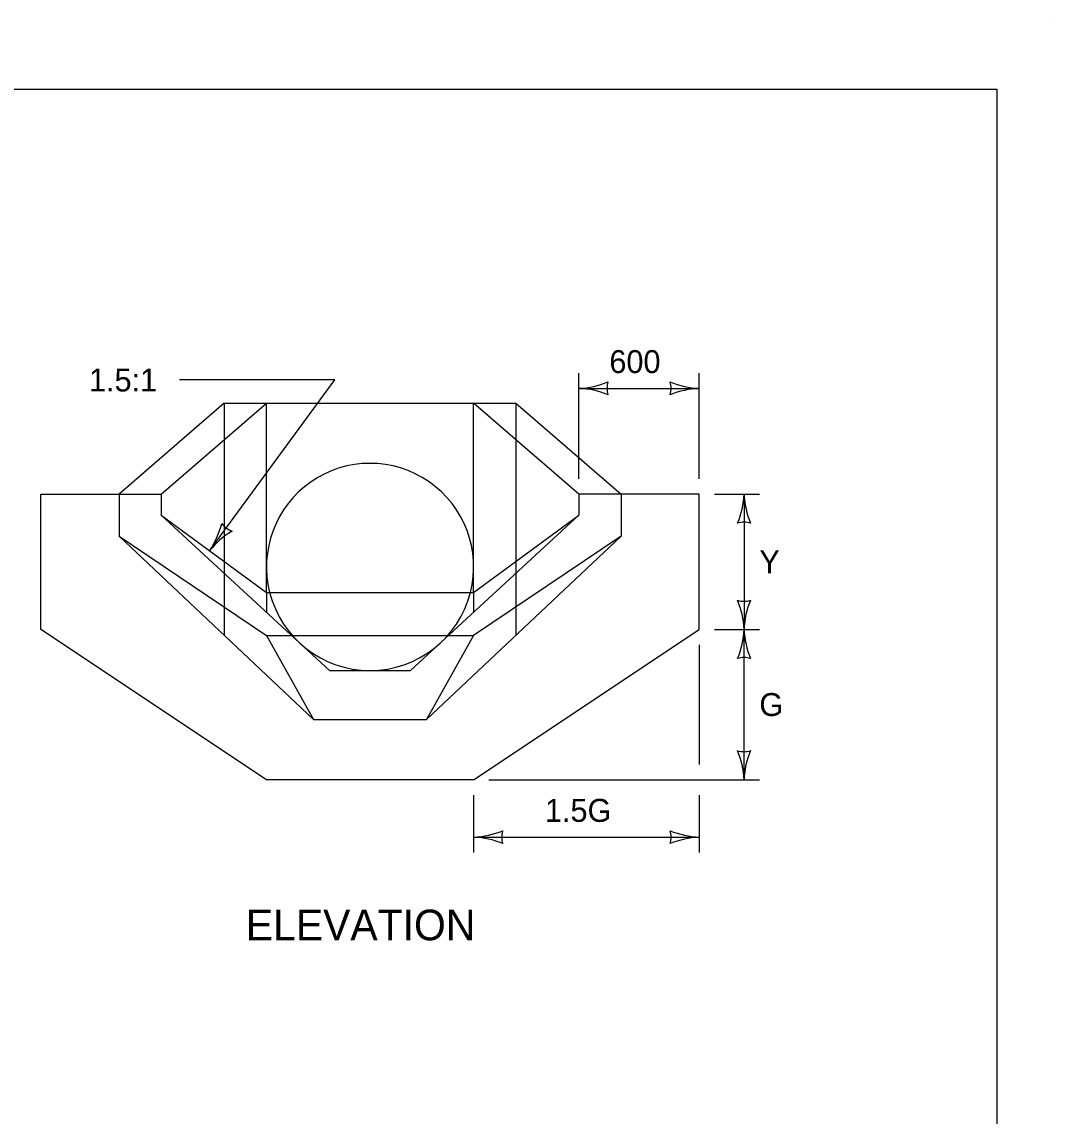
# Model space of a CAD drawing. Extents: x 49991.4 to 50043, y 49987.6 to 50011.4.
# Drawn here: x 50014.2 to 50016.9, y 49996.314 to 49999.176 of the extents above; entities that cross this region are included whole.
import ezdxf

# ---------------------------------------------------------------- set-up
doc = ezdxf.new("R2010")
doc.units = 0
for name, color, linetype in [('Level 1', 7, 'Continuous'), ('Level 2', 7, 'Continuous'), ('Level 3', 7, 'Continuous'), ('Level 4', 7, 'Continuous')]:
    doc.layers.add(name, color=color, linetype=linetype)

msp = doc.modelspace()

# ---------------------------------------------------------------- linework, layer by layer
at = {"layer": 'Level 1'}
for p, q in [((50016.9001, 49999.1756), (50016.9001, 49999.1756)), ((50014.7294, 49998.1783), (50014.4542, 49997.9407)), ((50014.5643, 49997.9407), (50014.8396, 49998.1783)), ((50014.7294, 49998.1783), (50015.4918, 49998.1783)), ((50014.8396, 49997.6834), (50014.8396, 49998.1783)), ((50015.3816, 49997.6834), (50015.3816, 49998.1783)), ((50015.657, 49997.9407), (50015.3816, 49998.1783)), ((50015.4918, 49998.1783), (50015.7671, 49997.9407)), ((50014.2497, 49997.5868), (50014.2497, 49997.9407)), ((50014.2497, 49997.9407), (50014.5643, 49997.9407)), ((50014.5643, 49997.9407), (50014.5643, 49997.8856)), ((50015.9716, 49997.9407), (50015.657, 49997.9407)), ((50015.657, 49997.9407), (50015.657, 49997.8856)), ((50015.9716, 49997.5868), (50015.9716, 49997.9407)), ((50014.5643, 49997.8856), (50014.8396, 49997.6834)), ((50015.3816, 49997.6834), (50015.657, 49997.8856)), ((50014.8396, 49997.6834), (50015.3816, 49997.6834)), ((50014.8396, 49997.1935), (50014.2497, 49997.5868)), ((50015.3816, 49997.1935), (50015.9716, 49997.5868)), ((50015.3816, 49997.1935), (50014.8396, 49997.1935))]:
    msp.add_line(p, q, dxfattribs=at)
msp.add_lwpolyline([(49999.3835, 49998.9992), (50016.7501, 49998.9992), (50016.7501, 49987.7988), (49999.3835, 49987.7988)], close=True, dxfattribs=at)
msp.add_arc((50015.1106, 49997.75), 0.271, 345.7745, 194.2255, dxfattribs=at)
at = {"layer": 'Level 3'}
for p, q in [((50015.657, 49997.9807), (50015.657, 49998.2571)), ((50015.9716, 49997.9807), (50015.9716, 49998.2571)), ((50015.0184, 49998.239), (50014.6121, 49998.239)), ((50014.691, 49997.7925), (50015.0184, 49998.239)), ((50015.657, 49998.2171), (50015.9716, 49998.2171)), ((50016.0116, 49997.9407), (50016.129, 49997.9407)), ((50016.089, 49997.9407), (50016.089, 49997.5868)), ((50016.0116, 49997.5868), (50016.129, 49997.5868)), ((50016.089, 49997.1935), (50016.089, 49997.5868)), ((50015.9716, 49997.5468), (50015.9716, 49997.2335)), ((50015.4216, 49997.1935), (50016.129, 49997.1935)), ((50015.3816, 49997.1535), (50015.3816, 49997.0034)), ((50015.9716, 49997.1535), (50015.9716, 49997.0034)), ((50015.3816, 49997.0434), (50015.9716, 49997.0434))]:
    msp.add_line(p, q, dxfattribs=at)
for centre, radius, start, end in [((50015.6455, 49998.4498), 0.233, 272.8273, 292.0772), ((50015.6478, 49997.995), 0.2223, 67.456, 87.6395), ((50015.7852, 49998.2171), 0.0548, 162.1388, 197.8612), ((50015.9808, 49998.4393), 0.2223, 247.456, 267.6395), ((50015.8434, 49998.2171), 0.0548, 342.1388, 17.8612), ((50015.9831, 49997.9844), 0.233, 92.8273, 112.0772), ((50015.8669, 49997.9499), 0.2223, 337.456, 357.6395), ((50016.3217, 49997.9522), 0.233, 182.8273, 202.0772), ((50014.4967, 49997.921), 0.233, 326.5303, 345.7801), ((50014.8646, 49997.6537), 0.2223, 121.159, 141.3425), ((50014.7669, 49997.8959), 0.0548, 215.8418, 251.5642), ((50016.089, 49997.8125), 0.0548, 72.1388, 107.8612), ((50016.089, 49997.715), 0.0548, 252.1388, 287.8612), ((50015.8563, 49997.5753), 0.233, 2.8273, 22.0772), ((50016.3111, 49997.5777), 0.2223, 157.456, 177.6395), ((50015.8669, 49997.596), 0.2223, 337.456, 357.6395), ((50016.3217, 49997.5983), 0.233, 182.8273, 202.0772), ((50016.089, 49997.4586), 0.0548, 72.1388, 107.8612), ((50016.089, 49997.3217), 0.0548, 252.1388, 287.8612), ((50015.8563, 49997.182), 0.233, 2.8273, 22.0772), ((50016.3111, 49997.1844), 0.2223, 157.456, 177.6395), ((50015.3701, 49997.2761), 0.233, 272.8273, 292.0772), ((50015.3724, 49996.8213), 0.2223, 67.456, 87.6395), ((50015.5098, 49997.0434), 0.0548, 162.1388, 197.8612), ((50015.9808, 49997.2656), 0.2223, 247.456, 267.6395), ((50015.8434, 49997.0434), 0.0548, 342.1388, 17.8612), ((50015.9831, 49996.8107), 0.233, 92.8273, 112.0772)]:
    msp.add_arc(centre, radius, start, end, dxfattribs=at)
at = {"layer": 'Level 4'}
for p, q in [((50014.7294, 49998.1783), (50014.7294, 49997.5711)), ((50015.4918, 49998.1783), (50015.4918, 49997.571)), ((50014.4542, 49997.9407), (50014.4542, 49997.8305)), ((50015.7671, 49997.9407), (50015.7671, 49997.8305)), ((50015.0046, 49997.479), (50014.5643, 49997.8856)), ((50015.2166, 49997.479), (50015.657, 49997.8856)), ((50014.4542, 49997.8305), (50014.963, 49997.3508)), ((50014.4542, 49997.8305), (50014.8396, 49997.571)), ((50015.7671, 49997.8305), (50015.2581, 49997.3508)), ((50015.7671, 49997.8305), (50015.3816, 49997.571)), ((50014.8396, 49997.6834), (50014.8396, 49997.6314)), ((50015.3816, 49997.6834), (50015.3816, 49997.6313)), ((50014.8396, 49997.571), (50015.3816, 49997.571)), ((50014.8396, 49997.571), (50014.963, 49997.3508)), ((50015.3816, 49997.571), (50015.2581, 49997.3508)), ((50015.0046, 49997.479), (50015.2166, 49997.479)), ((50014.963, 49997.3508), (50015.2581, 49997.3508))]:
    msp.add_line(p, q, dxfattribs=at)
msp.add_arc((50015.1106, 49997.75), 0.271, 194.2255, 345.7745, dxfattribs=at)

# ---------------------------------------------------------------- texts
at = {"layer": 'Level 2'}
for s, height, p in [('600', 0.06, (50015.7366, 49998.2571)), ('1.5:1', 0.06, (50014.3753, 49998.209)), ('Y', 0.06, (50016.129, 49997.7338)), ('G', 0.06, (50016.129, 49997.3602)), ('1.5G', 0.06, (50015.568, 49997.0834)), ('ELEVATION', 0.08, (50014.7856, 49996.7738))]:
    msp.add_text(s, height=height, dxfattribs=at).set_placement(p)

doc.saveas('drawing.dxf')
